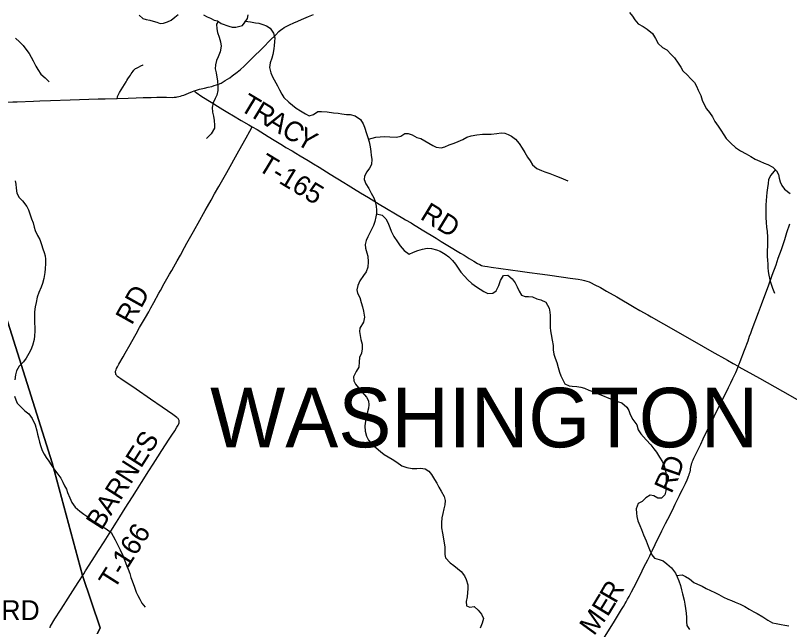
# Model space of a CAD drawing. Extents: x 1451455 to 1749751, y 218250 to 574981.
# Drawn here: x 1579778 to 1591490, y 357020 to 366262 of the extents above; entities that cross this region are included whole.
import ezdxf

# ---------------------------------------------------------------- set-up
doc = ezdxf.new("R2010")
doc.units = 0
for name, color, linetype in [('GM_X_County_Road', 7, 'Continuous'), ('GM_X_County_Road_Text', 7, 'Continuous'), ('GM_X_Major_River', 7, 'Continuous'), ('GM_X_Minor_River', 7, 'Continuous'), ('GM_X_Township', 7, 'Continuous'), ('GM_X_Township_Road', 7, 'Continuous'), ('GM_X_Township_Road_Text', 7, 'Continuous'), ('GM_X_Township_Text', 7, 'Continuous')]:
    doc.layers.add(name, color=color, linetype=linetype)

msp = doc.modelspace()

# ---------------------------------------------------------------- linework, layer by layer
at = {"layer": 'GM_X_County_Road'}
for points in [[(1582481, 365121), (1582489, 365124), (1582517, 365133), (1582564, 365145), (1582637, 365162), (1582694, 365176), (1582748, 365190), (1582786, 365201), (1582821, 365212), (1582852, 365224), (1582888, 365240), (1582920, 365257), (1582953, 365277), (1582984, 365296), (1583019, 365320), (1583059, 365349), (1583133, 365403), (1583182, 365443), (1583236, 365495), (1583297, 365555), (1583353, 365609), (1583401, 365654), (1583481, 365732), (1583530, 365780), (1583628, 365882), (1583715, 365971), (1583765, 366018), (1583794, 366044), (1583817, 366062), (1583844, 366079), (1583876, 366097), (1583925, 366121), (1583991, 366151), (1584048, 366175), (1584108, 366201), (1584214, 366245), (1584286, 366276)], [(1581319, 365007), (1581482, 365011), (1581603, 365015), (1581708, 365019), (1581832, 365022), (1581918, 365024), (1581986, 365026), (1582062, 365027), (1582157, 365023), (1582179, 365024), (1582207, 365026), (1582224, 365029), (1582250, 365035), (1582275, 365040), (1582302, 365049), (1582324, 365056), (1582362, 365071), (1582396, 365086), (1582459, 365113), (1582481, 365121)], [(1579540, 364941), (1579583, 364945), (1579648, 364951), (1579739, 364956), (1579805, 364958), (1580051, 364967), (1580146, 364971), (1580310, 364977), (1580604, 364986), (1580745, 364991), (1581027, 365000), (1581135, 365003), (1581319, 365007)], [(1590715, 360956), (1590727, 360988), (1590743, 361029), (1590807, 361201), (1590862, 361342), (1590886, 361410), (1590903, 361456), (1590927, 361519), (1591020, 361769), (1591065, 361890), (1591100, 361985), (1591170, 362174), (1591229, 362332), (1591286, 362489), (1591320, 362589), (1591367, 362724), (1591417, 362873), (1591451, 362977), (1591495, 363111)], [(1588652, 356795), (1588842, 357101), (1588949, 357275), (1588977, 357322), (1589004, 357368), (1589017, 357392), (1589041, 357433), (1589064, 357475), (1589101, 357544), (1589134, 357609), (1589169, 357678), (1589219, 357779), (1589243, 357827), (1589276, 357896), (1589316, 357974), (1589344, 358030), (1589374, 358090), (1589397, 358136), (1589416, 358174), (1589459, 358261), (1589510, 358366), (1589541, 358430), (1589560, 358468), (1589615, 358576), (1589648, 358643), (1589692, 358731), (1589738, 358824), (1589762, 358872), (1589795, 358939), (1589810, 358969), (1589827, 359003), (1589843, 359037), (1589870, 359092), (1589895, 359142), (1589914, 359183), (1589939, 359237), (1589951, 359264), (1589964, 359294), (1589971, 359314), (1589979, 359337), (1589983, 359349), (1589986, 359358), (1589988, 359369), (1589991, 359381), (1589994, 359403), (1589998, 359431), (1590002, 359453), (1590005, 359466), (1590009, 359482), (1590015, 359502), (1590022, 359521), (1590031, 359543), (1590042, 359568), (1590051, 359588), (1590066, 359618), (1590146, 359780), (1590183, 359857), (1590235, 359962), (1590329, 360152), (1590377, 360250), (1590464, 360427), (1590568, 360637), (1590602, 360705), (1590634, 360770), (1590658, 360823), (1590676, 360863), (1590692, 360899), (1590707, 360936), (1590715, 360956)]]:
    msp.add_lwpolyline(points, dxfattribs=at)
at = {"layer": 'GM_X_Major_River'}
for points in [[(1581651, 366265), (1581704, 366217), (1581756, 366203), (1581809, 366193), (1581862, 366174), (1581915, 366159), (1581968, 366140), (1582020, 366145), (1582078, 366164), (1582136, 366193), (1582188, 366236), (1582241, 366279)], [(1582625, 366270), (1582678, 366241), (1582731, 366222), (1582783, 366193), (1582836, 366179), (1582889, 366140), (1583004, 366102), (1583057, 366087), (1583110, 366083), (1583215, 366111), (1583254, 366164), (1583287, 366217), (1583301, 366270)]]:
    msp.add_lwpolyline(points, dxfattribs=at)
at = {"layer": 'GM_X_Minor_River'}
for points in [[(1589068, 366309), (1589112, 366250), (1589147, 366194), (1589198, 366135), (1589275, 366093), (1589334, 366053), (1589415, 365991), (1589462, 365916), (1589503, 365838), (1589568, 365775), (1589634, 365742), (1589701, 365670), (1589750, 365620), (1589803, 365543), (1589846, 365482), (1589875, 365427), (1589944, 365358), (1589993, 365307), (1590050, 365250), (1590081, 365194), (1590109, 365133), (1590147, 365049), (1590168, 364982), (1590199, 364916), (1590234, 364849), (1590280, 364794), (1590325, 364729), (1590361, 364659), (1590412, 364588), (1590453, 364525), (1590496, 364458), (1590530, 364402), (1590600, 364330), (1590675, 364263), (1590747, 364216), (1590834, 364167), (1590905, 364127), (1590972, 364088), (1591042, 364057), (1591105, 364028), (1591161, 364007), (1591236, 363968), (1591295, 363913), (1591321, 363858), (1591334, 363800), (1591347, 363748), (1591374, 363691), (1591415, 363633), (1591498, 363567)], [(1582845, 366172), (1582820, 366131), (1582825, 366061), (1582836, 366002), (1582861, 365932), (1582882, 365864), (1582891, 365797), (1582874, 365711), (1582845, 365634), (1582820, 365580), (1582807, 365514), (1582800, 365456), (1582815, 365392), (1582827, 365327), (1582834, 365271), (1582841, 365193), (1582838, 365125), (1582827, 365059), (1582802, 365007), (1582769, 364942), (1582756, 364870), (1582761, 364797), (1582774, 364739), (1582785, 364673), (1582790, 364605), (1582788, 364555), (1582741, 364471), (1582668, 364400)], [(1583236, 366140), (1583254, 366177), (1583332, 366164), (1583410, 366152), (1583461, 366144), (1583523, 366123), (1583575, 366106), (1583630, 366071), (1583683, 365996), (1583702, 365922), (1583699, 365864), (1583693, 365808), (1583688, 365758), (1583671, 365674), (1583656, 365618), (1583633, 365546), (1583622, 365476), (1583643, 365394), (1583666, 365335), (1583744, 365198), (1583775, 365137), (1583810, 365073), (1583837, 365020), (1583916, 364949), (1583968, 364906), (1584027, 364859), (1584090, 364818), (1584168, 364773), (1584221, 364744), (1584289, 364763), (1584354, 364808), (1584408, 364810), (1584494, 364806), (1584589, 364789), (1584659, 364782), (1584715, 364775), (1584789, 364766), (1584841, 364763), (1584916, 364744), (1585000, 364687), (1585039, 364624), (1585060, 364572), (1585091, 364479), (1585112, 364417), (1585131, 364350), (1585144, 364274), (1585153, 364204), (1585162, 364142), (1585169, 364089), (1585166, 364009), (1585137, 363954), (1585096, 363898), (1585058, 363833), (1585055, 363783), (1585080, 363716), (1585123, 363647), (1585160, 363573), (1585199, 363502), (1585220, 363450), (1585235, 363377), (1585242, 363317), (1585241, 363267), (1585231, 363215), (1585214, 363147), (1585197, 363085), (1585148, 362994), (1585109, 362914), (1585086, 362860), (1585069, 362799), (1585072, 362740), (1585093, 362670), (1585110, 362620), (1585117, 362537), (1585108, 362457), (1585085, 362386), (1585046, 362330), (1584991, 362247), (1584958, 362179), (1584943, 362111), (1584953, 362061), (1584986, 361996), (1585009, 361922), (1585028, 361855), (1585045, 361789), (1585061, 361697), (1585046, 361623), (1584987, 361531), (1584984, 361481), (1584992, 361421), (1585005, 361363), (1585022, 361290), (1585023, 361218), (1585012, 361152), (1584985, 361091), (1584976, 361021), (1584971, 360943), (1584934, 360877), (1584895, 360795), (1584900, 360737), (1584923, 360685), (1584967, 360632)], [(1579776, 365920), (1579837, 365861), (1579892, 365806), (1579935, 365752), (1579984, 365687), (1580013, 365630), (1580045, 365578), (1580087, 365497), (1580115, 365447), (1580164, 365376), (1580227, 365319), (1580290, 365258)], [(1585119, 364391), (1585230, 364419), (1585298, 364424), (1585358, 364429), (1585442, 364428), (1585541, 364421), (1585610, 364438), (1585668, 364479), (1585720, 364476), (1585780, 364455), (1585853, 364418), (1585911, 364399), (1585972, 364364), (1586091, 364295), (1586143, 364272), (1586218, 364259), (1586273, 364276), (1586339, 364303), (1586417, 364330), (1586478, 364355), (1586546, 364386), (1586610, 364421), (1586675, 364440), (1586757, 364459), (1586845, 364466), (1586919, 364465), (1586977, 364468), (1587061, 364477), (1587125, 364486), (1587181, 364483), (1587232, 364462), (1587284, 364436), (1587343, 364393), (1587398, 364324), (1587445, 364257), (1587486, 364188), (1587525, 364117), (1587568, 364063), (1587603, 364002), (1587665, 363947), (1587736, 363918), (1587788, 363897), (1587861, 363872), (1587913, 363853), (1587965, 363831), (1588032, 363808), (1588136, 363760)], [(1591276, 363931), (1591205, 363846), (1591172, 363779), (1591165, 363719), (1591156, 363657), (1591149, 363585), (1591142, 363525), (1591139, 363463), (1591134, 363392), (1591132, 363332), (1591133, 363280), (1591134, 363204), (1591135, 363130), (1591144, 363060), (1591151, 362993), (1591155, 362907), (1591157, 362851), (1591156, 362779), (1591153, 362703), (1591153, 362623), (1591157, 362558), (1591160, 362504), (1591163, 362448), (1591168, 362388), (1591177, 362332), (1591190, 362265), (1591206, 362215), (1591234, 362136), (1591261, 362062)], [(1579775, 363762), (1579783, 363710), (1579790, 363648), (1579801, 363574), (1579834, 363511), (1579883, 363460), (1579950, 363373), (1579975, 363321), (1579996, 363264), (1580023, 363184), (1580044, 363125), (1580063, 363059), (1580074, 363009), (1580113, 362934), (1580146, 362875), (1580171, 362799), (1580194, 362732), (1580212, 362676), (1580225, 362626), (1580230, 362576), (1580233, 362510), (1580228, 362431), (1580223, 362375), (1580206, 362284), (1580185, 362210), (1580166, 362150), (1580131, 362070), (1580108, 362002), (1580089, 361923), (1580076, 361857), (1580067, 361777), (1580064, 361692), (1580067, 361608), (1580070, 361548), (1580071, 361486), (1580068, 361418), (1580059, 361360), (1580034, 361270), (1580009, 361204), (1579982, 361147), (1579939, 361081), (1579899, 361024), (1579836, 360956), (1579795, 360885), (1579780, 360829), (1579767, 360753)], [(1585241, 363264), (1585327, 363244), (1585384, 363185), (1585413, 363132), (1585440, 363056), (1585461, 362997), (1585502, 362919), (1585557, 362840), (1585600, 362777), (1585659, 362708), (1585734, 362651), (1585803, 362684), (1585865, 362707), (1585937, 362728), (1586007, 362741), (1586073, 362736), (1586149, 362719), (1586206, 362698), (1586280, 362653), (1586333, 362610), (1586390, 362557), (1586435, 362498), (1586475, 362442), (1586518, 362381), (1586571, 362318), (1586624, 362265), (1586683, 362210), (1586752, 362157), (1586808, 362122), (1586863, 362085), (1586923, 362058), (1586999, 362063), (1587051, 362095), (1587092, 362176), (1587119, 362252), (1587164, 362329), (1587228, 362336), (1587292, 362279), (1587337, 362217), (1587370, 362156), (1587401, 362090), (1587436, 362033), (1587492, 362012), (1587543, 362013), (1587601, 362004), (1587669, 361977), (1587725, 361961), (1587802, 361927), (1587851, 361836), (1587864, 361772), (1587869, 361722), (1587870, 361634), (1587867, 361544), (1587872, 361494), (1587883, 361439), (1587900, 361353), (1587913, 361270), (1587916, 361204), (1587925, 361140), (1587942, 361080), (1587967, 361015), (1587988, 360937), (1588011, 360868), (1588030, 360812), (1588053, 360761), (1588092, 360689), (1588158, 360658), (1588202, 360657), (1588271, 360652), (1588333, 360639), (1588389, 360624), (1588454, 360595), (1588542, 360562), (1588597, 360541), (1588661, 360516), (1588754, 360475), (1588824, 360448), (1588887, 360425), (1588955, 360403), (1589028, 360338), (1589057, 360288), (1589080, 360227), (1589119, 360149), (1589178, 360068), (1589201, 359997), (1589242, 359934), (1589321, 359845), (1589394, 359770), (1589437, 359709), (1589476, 359658), (1589523, 359583), (1589568, 359509), (1589593, 359448), (1589612, 359382), (1589622, 359293), (1589622, 359243), (1589619, 359173), (1589618, 359123), (1589619, 359071), (1589602, 359013), (1589554, 358960)], [(1584967, 360632), (1585024, 360563), (1585088, 360488), (1585120, 360433), (1585127, 360373), (1585120, 360321), (1585095, 360229), (1585080, 360152), (1585071, 360098), (1585066, 360048), (1585069, 359975), (1585088, 359899), (1585119, 359838), (1585174, 359773), (1585235, 359722), (1585299, 359667), (1585358, 359620), (1585419, 359588), (1585477, 359549), (1585546, 359506), (1585625, 359452), (1585699, 359423), (1585781, 359412), (1585852, 359411), (1585908, 359414), (1585978, 359403), (1586032, 359370), (1586071, 359318), (1586120, 359243), (1586153, 359188), (1586184, 359128), (1586219, 359067), (1586264, 358988), (1586281, 358928), (1586276, 358858), (1586261, 358802), (1586244, 358730), (1586229, 358662), (1586222, 358586), (1586225, 358514), (1586240, 358433), (1586255, 358347), (1586266, 358283), (1586275, 358227), (1586276, 358170), (1586276, 358110), (1586287, 358060), (1586354, 357985), (1586411, 357942), (1586464, 357899), (1586522, 357852), (1586571, 357785), (1586598, 357729), (1586621, 357650), (1586622, 357592), (1586619, 357532), (1586612, 357468), (1586595, 357398), (1586602, 357334), (1586654, 357315), (1586718, 357322), (1586777, 357265), (1586830, 357208), (1586859, 357140), (1586838, 357070), (1586809, 356994)], [(1579765, 360505), (1579783, 360446)], [(1579783, 360446), (1579806, 360396), (1579869, 360331), (1579922, 360280), (1579978, 360237), (1580032, 360164), (1580075, 360069), (1580100, 359979), (1580111, 359929), (1580124, 359874), (1580143, 359806), (1580164, 359743), (1580184, 359683), (1580211, 359629), (1580244, 359578), (1580283, 359523), (1580320, 359465), (1580369, 359392), (1580418, 359323), (1580463, 359264), (1580496, 359202), (1580520, 359149), (1580551, 359099), (1580566, 359048), (1580599, 358964), (1580632, 358895), (1580683, 358824), (1580752, 358765), (1580811, 358718), (1580871, 358677), (1580944, 358624), (1581013, 358583), (1581085, 358538), (1581152, 358497), (1581225, 358442), (1581258, 358387), (1581287, 358329), (1581320, 358262), (1581361, 358179), (1581402, 358095), (1581423, 358038), (1581444, 357988), (1581464, 357935), (1581485, 357885), (1581506, 357823), (1581525, 357760), (1581542, 357710), (1581577, 357615), (1581606, 357541), (1581629, 357488), (1581660, 357432), (1581690, 357375), (1581739, 357312)], [(1589554, 358960), (1589500, 358962), (1589436, 358996), (1589383, 359006), (1589316, 358965), (1589261, 358910), (1589199, 358881), (1589172, 358799), (1589175, 358733), (1589180, 358683), (1589195, 358618), (1589224, 358550), (1589249, 358489), (1589282, 358407), (1589323, 358318), (1589352, 358237), (1589373, 358183), (1589408, 358104), (1589445, 358053), (1589519, 358032), (1589578, 358011), (1589636, 357970), (1589705, 357909), (1589765, 357828), (1589792, 357772), (1589816, 357709), (1589839, 357639), (1589856, 357576), (1589873, 357516), (1589895, 357419), (1589904, 357359), (1589915, 357293), (1589926, 357224), (1589933, 357158), (1589933, 357090), (1589934, 357036), (1589979, 356977)], [(1589782, 357793), (1589867, 357801), (1589918, 357778), (1589978, 357743), (1590043, 357688), (1590098, 357661), (1590168, 357628), (1590227, 357597), (1590293, 357566), (1590362, 357534), (1590420, 357504), (1590491, 357462), (1590558, 357435), (1590612, 357414), (1590666, 357387), (1590741, 357356), (1590814, 357321), (1590880, 357284), (1590949, 357243), (1591003, 357216), (1591084, 357167), (1591163, 357117), (1591232, 357078), (1591286, 357065), (1591364, 357050), (1591417, 357041), (1591481, 357028)]]:
    msp.add_lwpolyline(points, dxfattribs=at)
at = {"layer": 'GM_X_Township'}
for points in [[(1578869, 364120), (1580333, 359498), (1580793, 357791), (1581059, 356999), (1578606, 351966)], [(1578606, 351966), (1581059, 356999), (1580793, 357791), (1580333, 359498), (1578869, 364120)]]:
    msp.add_lwpolyline(points, dxfattribs=at)
at = {"layer": 'GM_X_Township_Road'}
for points in [[(1581319, 365007), (1581320, 365026), (1581322, 365038), (1581331, 365059), (1581352, 365096), (1581429, 365216), (1581452, 365256), (1581464, 365277), (1581480, 365303), (1581504, 365339), (1581516, 365358), (1581528, 365377), (1581543, 365398), (1581557, 365420), (1581569, 365436), (1581580, 365447), (1581593, 365458), (1581609, 365467), (1581638, 365481), (1581676, 365499), (1581709, 365513), (1581712, 365515)], [(1582481, 365121), (1582499, 365105), (1582511, 365095), (1582596, 365038), (1582738, 364950), (1582766, 364933), (1582835, 364890), (1582915, 364840), (1582993, 364793), (1583075, 364744), (1583194, 364675), (1583307, 364609), (1583360, 364577)], [(1581256, 358517), (1581271, 358541), (1581306, 358597), (1581356, 358678), (1581438, 358809), (1581550, 358983), (1581609, 359077), (1581687, 359198), (1581798, 359373), (1581862, 359476), (1581930, 359584), (1581994, 359684), (1582105, 359854), (1582144, 359915), (1582187, 359981), (1582222, 360033), (1582241, 360063), (1582246, 360074), (1582250, 360084), (1582254, 360100), (1582255, 360108), (1582255, 360113), (1582255, 360126), (1582253, 360136), (1582250, 360145), (1582243, 360157), (1582239, 360164), (1582230, 360173), (1582222, 360181), (1582201, 360198), (1582159, 360229), (1581997, 360340), (1581821, 360461), (1581605, 360610), (1581523, 360665), (1581469, 360702), (1581373, 360766), (1581341, 360788), (1581323, 360803), (1581314, 360812), (1581308, 360820), (1581303, 360827), (1581299, 360834), (1581297, 360841), (1581295, 360850), (1581293, 360858), (1581293, 360865), (1581293, 360873), (1581294, 360881), (1581300, 360902), (1581307, 360920), (1581320, 360947), (1581342, 360987), (1581406, 361098), (1581439, 361155), (1581514, 361286), (1581583, 361409), (1581604, 361446), (1581656, 361540), (1581747, 361696), (1581796, 361781), (1581828, 361839), (1581873, 361922), (1581949, 362060), (1581973, 362103), (1582030, 362207), (1582109, 362347), (1582142, 362404), (1582172, 362458), (1582199, 362507), (1582224, 362553), (1582273, 362639), (1582337, 362753), (1582373, 362819), (1582473, 362996), (1582497, 363039), (1582543, 363122), (1582650, 363311), (1582685, 363374), (1582741, 363470), (1582792, 363562), (1582854, 363674), (1582896, 363748), (1582977, 363887), (1583160, 364213), (1583268, 364412), (1583324, 364512), (1583360, 364577)], [(1583360, 364577), (1583434, 364535), (1583602, 364433), (1583692, 364378), (1583820, 364298), (1583870, 364267), (1583963, 364213), (1584019, 364180), (1584084, 364141), (1584206, 364070), (1584287, 364020), (1584372, 363965), (1584483, 363896), (1584542, 363860), (1584745, 363735), (1584812, 363694), (1584893, 363645), (1584999, 363581), (1585120, 363510), (1585282, 363409), (1585639, 363198), (1585682, 363173), (1585763, 363124), (1585800, 363102), (1585850, 363072), (1585932, 363021), (1586142, 362895), (1586221, 362844), (1586320, 362785), (1586513, 362666), (1586566, 362634), (1586645, 362587), (1586715, 362544), (1586771, 362511), (1586806, 362494), (1586830, 362480), (1586849, 362475), (1586879, 362469), (1586918, 362463), (1586976, 362455), (1587415, 362395), (1587554, 362376), (1587710, 362355), (1587827, 362337), (1588070, 362302), (1588171, 362288), (1588292, 362272), (1588347, 362263), (1588386, 362255), (1588421, 362245), (1588458, 362232), (1588491, 362217), (1588535, 362195), (1588628, 362145), (1588722, 362092), (1588876, 362004), (1589140, 361852), (1589225, 361802), (1589344, 361733), (1589398, 361702), (1589584, 361597), (1590051, 361330), (1590313, 361181), (1590551, 361048), (1590639, 360997), (1590715, 360956)], [(1590715, 360956), (1590725, 360950), (1590934, 360832), (1591034, 360776), (1591383, 360579), (1591606, 360454)], [(1580810, 357818), (1580839, 357863), (1580936, 358016), (1581035, 358171), (1581118, 358300), (1581221, 358461), (1581256, 358517)], [(1580301, 356998), (1580304, 357010), (1580309, 357024), (1580375, 357136), (1580460, 357269), (1580513, 357352), (1580538, 357391), (1580645, 357560), (1580726, 357687), (1580810, 357818)]]:
    msp.add_lwpolyline(points, dxfattribs=at)

# ---------------------------------------------------------------- texts
at = {"layer": 'GM_X_County_Road_Text'}
for s, rotation, p in [('D', 70.8611, (1589816, 359270)), ('R', 65.6365, (1589704, 359018)), ('R', 60.105, (1588858, 357353)), ('E', 58.6519, (1588737, 357154)), ('RD', 0, (1579565, 357117)), ('M', 53.9762, (1588531, 356868))]:
    msp.add_text(s, height=300, rotation=rotation, dxfattribs=at).set_placement(p)
at = {"layer": 'GM_X_Township_Road_Text'}
for s, rotation, p in [('T', 328.8341, (1583154, 364840)), ('R', 328.8351, (1583346, 364724)), ('A', 328.8378, (1583557, 364596)), ('C', 328.9635, (1583784, 364459)), ('Y', 330.1826, (1584001, 364329)), ('T-165', 328.7573, (1583425, 363933)), ('RD', 328.6214, (1585886, 363192)), ('RD', 60.8025, (1581538, 361567)), ('BARNES', 57.5808, (1581079, 358461)), ('T-166', 57.7081, (1581273, 357567))]:
    msp.add_text(s, height=300, rotation=rotation, dxfattribs=at).set_placement(p)
at = {"layer": 'GM_X_Township_Text'}
msp.add_text('WASHINGTON', height=900, rotation=0, dxfattribs=at).set_placement((1582724, 359730))

doc.saveas('drawing.dxf')
